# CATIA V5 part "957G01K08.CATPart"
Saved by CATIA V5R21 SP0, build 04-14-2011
Part number: 957G01K08
Bounding box of the stored display mesh (mm): x -33.75 to 33.05, y -127.5 to 127.5, z -8 to 12
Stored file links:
  C:\Users\ALI OZGUN\Desktop\alhan\TESLIMEDILEN3\957G01K08.CATPart
  C:\Users\ALI OZGUN\Desktop\alhan\TESLIMEDILEN3\960B01P01.CATPart
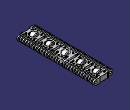
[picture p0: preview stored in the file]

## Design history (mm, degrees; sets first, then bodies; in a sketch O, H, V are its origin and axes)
Set1
  Plane1: type Normal, Curve Sketch5, RefPoint Sketch5.P3
  Point1: type Center, Curve edge [face of Pad1 from Sketch1.L2 | face of Pocket3 from Sketch4.A1]
  Line1: type PtDir, RefPoint Point1, Direction face of Pad1 from Sketch1.L2, Start 0, End 20
Body1 (main body)
  Sketch1 on zx-plane, origin (0, 0, 0), H (-1, 0, 0), V (0, 0, 1)
    construction line L1 (-25.05, 0) -> (25.75, 0)
    point P1 (-25.05, 0)
    line L2 (-25.05, 8) -> (25.75, 8)
    line L3 (25.75, -8) -> (-25.05, -8)
    arc A1 centre (25.75, 0) radius 8 from (25.75, 8) to (25.75, -8) cw
    arc A2 centre (-25.05, 0) radius 8 from (-25.05, -8) to (-25.05, 8) cw
    distance L1 L2 = 8
    distance P1 V = 25.05
    length L1 = 50.8
    coincidence: P1 H
    horizontal: L1 H
    tangency: A1 L2, A2 L2, A1 L3, A2 L3
  Pad1: profile Sketch1, direction (0, 1, 0), length 127.5, mirrored extent
  Sketch2 on face of Pad1 from Sketch1.L2, origin (0, 0, 8), H (1, 0, 0), V (0, 1, 0)
    line L1 (-50.9731, -119.3) -> (-16.75, -119.3)
    line L2 (-15.75, -120.3) -> (-15.75, -122.5)
    line L3 (-16.75, -123.5) -> (-50.9731, -123.5)
    line L4 (-50.9731, -123.5) -> (-50.9731, -119.3)
    arc A1 centre (-16.75, -120.3) radius 1 from (-16.75, -119.3) to (-15.75, -120.3) cw
    arc A2 centre (-16.75, -122.5) radius 1 from (-15.75, -122.5) to (-16.75, -123.5) cw
    reference projected line E1 (-25.75, -127.5) -> (25.05, -127.5) from edge [start face of Pad1 | face of Pad1 from Sketch1.L2]
    reference projected line E2 through (-25.75, 0) direction (0, 1) from axis of face of Pad1 from Sketch1.A1
    radius A1 = 1
    radius A2 = 1 {= Sketch2.radius(A1)}
    length L4 = 4.2
    distance L3 E1 = 4
    distance L2 E2 = 10
    horizontal: L1 H, L3 H
    vertical: L2 V, L4 V
    tangency: A1 L1, A1 L2, A2 L2, A2 L3
  Pocket1: profile Sketch2, direction (0, 0, -1), length 30, mirrored extent
  RectPattern1: of Pocket1, direction 1 instances 32, spacing 8.2, along axis of face of Pad1 from Sketch1.A1
  Sketch3 on face of Pad1 from Sketch1.L2, origin (0, 0, 8), H (1, 0, 0), V (0, 1, 0)
    line L1 (50.2731, -123.4) -> (50.2731, -127.6)
    line L2 (50.2731, -127.6) -> (16.05, -127.6)
    arc A1 centre (16.0504, -126.5996) radius 1.0004 from (16.05, -127.6) to (15.05, -126.6) cw
    line L3 (15.05, -126.6) -> (15.05, -124.4)
    arc A2 centre (16.0504, -124.4004) radius 1.0004 from (15.05, -124.4) to (16.05, -123.4) cw
    line L4 (16.05, -123.4) -> (50.2731, -123.4)
    reference projected line E2 through (25.05, 0) direction (0, 1) from axis of face of Pad1 from Sketch1.A2
    reference projected line E3 (-25.75, -127.5) -> (25.05, -127.5) from edge [start face of Pad1 | face of Pad1 from Sketch1.L2]
    distance L3 E2 = 10
    distance L4 E3 = 4.1
  Pocket2: profile Sketch3, direction (0, 0, -1), length 30
  RectPattern2: of Pocket2, direction 1 instances 32, spacing 8.2, along axis of face of Pad1 from Sketch1.A2
  RemoveFace1: RemoveFaces (face of RectPattern2; face of RectPattern2)
  RemoveFace2: RemoveFaces (face of RectPattern1; face of RectPattern1; face of Pad1 from Sketch1.A1)
  Sketch4 on face of Pad1 from Sketch1.L2, origin (0, 0, 8), H (1, 0, 0), V (0, 1, 0)
    circle A1 centre (0, -101.5) radius 12
    point P1 (0, -101.5)
    point P2 (-13, -84.5)
    line L1 (-12, -84.5) -> (-7.7574, -84.5)
    line L2 (13, -85.5) -> (13, -89.7426)
    line L3 (-7.7574, -118.5) -> (-12, -118.5)
    line L4 (-13, -117.5) -> (-13, -113.2574)
    point P3 (13, -84.5)
    point P4 (13, -118.5)
    point P5 (-13, -118.5)
    reference projected line E1 (-25.75, -127.5) -> (25.05, -127.5) from edge [start face of Pad1 | face of Pad1 from Sketch1.L2]
    line L5 (7.0503, -86.2071) -> (11.2929, -90.4497)
    line L6 (-7.0503, -86.2071) -> (-11.2929, -90.4497)
    line L7 (-11.2929, -112.5503) -> (-7.0503, -116.7929)
    line L8 (7.0503, -116.7929) -> (11.2929, -112.5503)
    arc A2 centre (12, -117.5) radius 1 from (12, -118.5) to (13, -117.5) ccw
    point P6 (12, -118.5)
    arc A3 centre (-12, -117.5) radius 1 from (-12, -118.5) to (-13, -117.5) cw
    arc A4 centre (-12, -85.5) radius 1 from (-12, -84.5) to (-13, -85.5) ccw
    arc A5 centre (12, -85.5) radius 1 from (12, -84.5) to (13, -85.5) cw
    line L9 (13, -113.2574) -> (13, -117.5)
    line L10 (7.7574, -84.5) -> (12, -84.5)
    line L11 (-13, -89.7426) -> (-13, -85.5)
    line L12 (12, -118.5) -> (7.7574, -118.5)
    arc A6 centre (12, -113.2574) radius 1 from (13, -113.2574) to (11.2929, -112.5503) ccw
    arc A7 centre (7.7574, -85.5) radius 1 from (7.7574, -84.5) to (7.0503, -86.2071) ccw
    arc A8 centre (12, -89.7426) radius 1 from (11.2929, -90.4497) to (13, -89.7426) ccw
    arc A9 centre (-7.7574, -85.5) radius 1 from (-7.7574, -84.5) to (-7.0503, -86.2071) cw
    arc A10 centre (-12, -89.7426) radius 1 from (-13, -89.7426) to (-11.2929, -90.4497) ccw
    arc A11 centre (-12, -113.2574) radius 1 from (-13, -113.2574) to (-11.2929, -112.5503) cw
    arc A12 centre (-7.7574, -117.5) radius 1 from (-7.0503, -116.7929) to (-7.7574, -118.5) cw
    arc A13 centre (7.7574, -117.5) radius 1 from (7.7574, -118.5) to (7.0503, -116.7929) cw
    point P42 (-13, -72.3)
    line L13 (-12, -72.3) -> (12, -72.3)
    line L14 (13, -73.3) -> (13, -78.3)
    line L15 (12, -79.3) -> (-12, -79.3)
    line L16 (-13, -78.3) -> (-13, -73.3)
    point P43 (13, -79.3)
    point P44 (-13, -79.3)
    arc A14 centre (-12, -73.3) radius 1 from (-12, -72.3) to (-13, -73.3) ccw
    point P45 (-12, -72.3)
    point P46 (-13, -73.3)
    arc A15 centre (12, -73.3) radius 1 from (12, -72.3) to (13, -73.3) cw
    point P48 (12, -72.3)
    point P49 (13, -73.3)
    arc A16 centre (12, -78.3) radius 1 from (13, -78.3) to (12, -79.3) cw
    point P51 (13, -78.3)
    point P52 (12, -79.3)
    arc A17 centre (-12, -78.3) radius 1 from (-12, -79.3) to (-13, -78.3) cw
    point P54 (-12, -79.3)
    point P55 (-13, -78.3)
    axis line L17 (15.2688, -101.5) -> (-36.2816, -101.5)
    point P59 (-13, -130.7)
    point P60 (13, -123.7)
    point P61 (-13, -123.7)
    point P62 (-12, -130.7)
    point P63 (-13, -129.7)
    point P65 (12, -130.7)
    point P66 (13, -129.7)
    point P68 (13, -124.7)
    point P69 (12, -123.7)
    point P71 (-12, -123.7)
    point P72 (-13, -124.7)
    line L18 (-12, -130.7) -> (12, -130.7)
    line L19 (13, -129.7) -> (13, -124.7)
    line L20 (12, -123.7) -> (-12, -123.7)
    line L21 (-13, -124.7) -> (-13, -129.7)
    arc A18 centre (-12, -129.7) radius 1 from (-12, -130.7) to (-13, -129.7) cw
    arc A19 centre (12, -129.7) radius 1 from (12, -130.7) to (13, -129.7) ccw
    arc A20 centre (12, -124.7) radius 1 from (13, -124.7) to (12, -123.7) ccw
    arc A21 centre (-12, -124.7) radius 1 from (-12, -123.7) to (-13, -124.7) ccw
    radius A1 = 12
    distance L1 L3 = 34
    distance L4 V = 13
    distance P1 L1 = 17
    distance L3 E1 = 9
    angle L5 L1 = 45
    angle L6 L1 = 45
    angle L7 L3 = 45
    angle L8 L3 = 135
    radius A2 = 1
    radius A3 = 1 {= Sketch4.radius(A2)}
    distance P2 P3 = 26
    radius A4 = 1 {= Sketch4.radius(A2)}
    radius A5 = 1 {= Sketch4.radius(A2)}
    distance L8 A2 = 5
    distance L7 A3 = 5
    distance L6 A4 = 5
    distance L5 A5 = 5
    radius A6 = 1
    radius A7 = 1 {= Sketch4.radius(A6)}
    radius A8 = 1 {= Sketch4.radius(A6)}
    radius A9 = 1 {= Sketch4.radius(A6)}
    radius A10 = 1 {= Sketch4.radius(A6)}
    radius A11 = 1 {= Sketch4.radius(A6)}
    radius A12 = 1 {= Sketch4.radius(A6)}
    radius A13 = 1 {= Sketch4.radius(A6)}
    distance L1 L15 = 5.2
    distance P44 P42 = 7
    radius A14 = 1
    radius A15 = 1 {= Sketch4.radius(A14)}
    radius A16 = 1 {= Sketch4.radius(A14)}
    radius A17 = 1 {= Sketch4.radius(A14)}
    coincidence: P1 V, L3 P4, L2 P4, L3 P5, L4 P5, L1 P2, L4 P2, L1 P3, L2 P3, L2 L9, L1 L10, L4 L11, P6 L3, P42 L4, P43 L2, L13 P42, L16 P42, L14 P43, L15 P43, L15 P44, L16 P44, L17 P1
    horizontal: L1 H, L3 H, L10 H, L13 H, L15 H, L17 H
    vertical: L2 V, L4 V, L9 V, L11 V, L14 V, L16 V
    tangency: A2 L3, A2 L2, A3 L3, A3 L4, A4 L1, A4 L4, A5 L1, A5 L2, L12 A2, A6 L9, A6 L8, A7 L10, A7 L5, A8 L5, A8 L2, A9 L1, A9 L6, A10 L11, A10 L6, A11 L4, A11 L7, A12 L7, A12 L3, A13 L12, A13 L8, A14 L13, A14 L16, A15 L13, A15 L14, A16 L14, A16 L15, A17 L15, A17 L16
    symmetry: P42 P59 L17, P43 P60 L17, P44 P61 L17, P45 P62 L17, P46 P63 L17, P48 P65 L17, P49 P66 L17, P51 P68 L17, P52 P69 L17, P54 P71 L17, P55 P72 L17, L13 L18 L17, L14 L19 L17, L15 L20 L17, L16 L21 L17, A14 A18 L17, A15 A19 L17, A16 A20 L17, A17 A21 L17
  Pocket3: profile Sketch4, direction (0, 0, -1), length 30
  RectPattern3: of Pocket3, direction 1 instances 5, spacing 51.4, along axis of face of Pad1 from Sketch1.A1
  Pocket4: profile Sketch7, direction (0, 1, 0), through (limit type 3)
Body2
  Solid1: linked copy from another document
  Translate1: Direction yz-plane, Length 50.8, ToTransfor Solid1
Body3
  Sketch5 on xy-plane, origin (0, 0, 0), H (1, 0, 0), V (0, 1, 0)
    point P1 (0, -101.5)
    reference projected circle E1 centre (0, -101.5) radius 12 from edge [face of Pad1 from Sketch1.L2 | face of Pocket3 from Sketch4.A1]
    line L1 (-12.5, -101.5) -> (12.5, -101.5)
    point P3 (12.5, -101.5)
    length L1 = 25
    distance P3 V = 12.5
    concentricity: P1 E1
    horizontal: L1 H
    coincidence: L1 P1
  Sketch6 on Plane1, origin (12.5, 0, 0), H (0, 1, 0), V (0, 0, 1)
    circle A1 centre (-101.5, 0) radius 1.5
    point P1 (-101.5, 0)
    reference projected point E1 (-101.5, 0) from Sketch5.P3
    radius A1 = 1.5
    coincidence: P1 E1
  Slot1: profile Sketch6, centre curve Sketch5
  Translate2: Direction xy-plane, Length 4, ToTransfor Slot1
  Rotate1: Axis Line1, Angle 90, ToTransfor Translate2
  RectPattern4: of the body so far, direction 1 instances 5, spacing 51.4, along axis of face of Pad1 from Sketch1.A2
  Sketch7 on start face of Pad1, origin (0, -127.5, 0), H (1, 0, 0), V (0, 0, 1)
    circle A1 centre (-25.75, 0) radius 3.5
    reference projected arc E1 centre (-25.75, 0) radius 8 from (-25.75, 8) to (-25.75, -8) ccw from edge [start face of Pad1 | face of Pad1 from Sketch1.A1]
    circle A2 centre (25.75, 0) radius 3.5
    radius A1 = 3.5
    concentricity: A1 E1
    symmetry: A1 A2 V
Body4
  Sketch8 on yz-plane, origin (0, 0, 0), H (0, 1, 0), V (0, 0, 1)
    circle A1 centre (-101.5, 4) radius 8
    circle A2 centre (-101.5, 3.7143) radius 1.75
    radius A1 = 8
    radius A2 = 1.75
  Pad2: profile Sketch8, direction (1, 0, 0), length 8, mirrored extent
  Fillet1: radius 2, on edge [face of Pad2 from Sketch8.A1 | end face of Pad2]; edge [start face of Pad2 | face of Pad2 from Sketch8.A1]
  Rotate2: Axis Line1, Angle 90, ToTransfor Fillet1
  RectPattern5: of the body so far, direction 1 instances 5, spacing 51.4, along axis of face of Pad1 from Sketch1.A2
